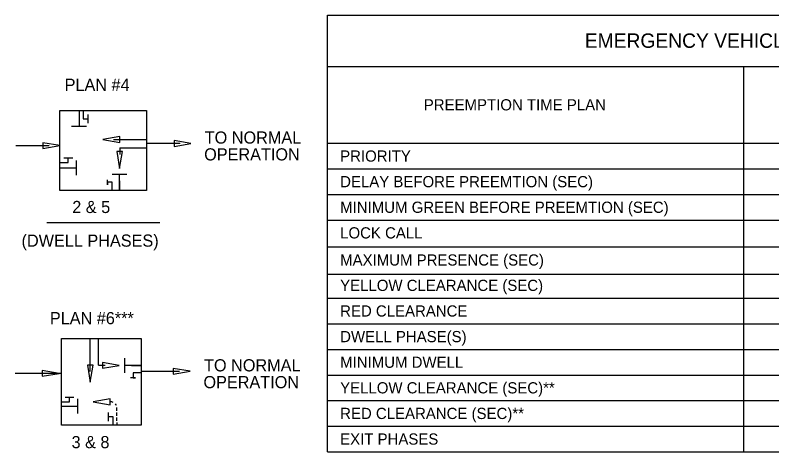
# Model space of a CAD drawing. Extents: x 0 to 1428, y -128 to 567.
# Drawn here: x 0.7203 to 1.0987, y 0.9823 to 1.2004 of the extents above; entities that cross this region are included whole.
import ezdxf

# ---------------------------------------------------------------- set-up
doc = ezdxf.new("R2010")
doc.units = 0
for name, color, linetype in [('SumBoxLines_dp', 7, 'Continuous'), ('TextLabel', 7, 'Continuous'), ('TextTables', 7, 'Continuous')]:
    doc.layers.add(name, color=color, linetype=linetype)

msp = doc.modelspace()

# ---------------------------------------------------------------- linework, layer by layer
at = {"layer": 'SumBoxLines_dp'}
for p, q in [((0.8764384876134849, 0.9822681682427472), (0.8764384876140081, 1.2004104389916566)), ((0.8764384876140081, 1.200410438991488), (1.3246048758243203, 1.200410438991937)), ((0.8764384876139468, 1.1748207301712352), (1.32460487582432, 1.1748207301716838)), ((1.0847013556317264, 0.9822681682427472), (1.0847013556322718, 1.1748207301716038)), ((0.8764384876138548, 1.1364361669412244), (1.32460487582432, 1.1364361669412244)), ((0.876438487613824, 1.1236413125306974), (1.1246852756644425, 1.1236413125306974)), ((0.8764384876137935, 1.110846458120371), (1.32460487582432, 1.110846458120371)), ((0.8764384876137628, 1.0980516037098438), (1.1646691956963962, 1.0980516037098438)), ((0.8764384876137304, 1.0846270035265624), (1.1246852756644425, 1.0846270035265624)), ((0.876438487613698, 1.0710904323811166), (1.1246852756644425, 1.0710904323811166)), ((0.8764384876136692, 1.0590372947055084), (1.32460487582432, 1.0590372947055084)), ((0.8764384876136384, 1.0462424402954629), (1.164669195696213, 1.0462424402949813)), ((0.8764384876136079, 1.0334475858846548), (1.32460487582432, 1.0334475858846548)), ((0.8764384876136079, 1.0334475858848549), (1.32460487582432, 1.0334475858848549)), ((0.8764384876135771, 1.020652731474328), (1.32460487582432, 1.020652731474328)), ((0.8764384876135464, 1.0078578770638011), (1.32460487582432, 1.0078578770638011)), ((0.8764384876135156, 0.9950630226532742), (1.3246048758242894, 0.9950630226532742)), ((0.8764384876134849, 0.9822681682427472), (1.3246048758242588, 0.9822681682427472))]:
    msp.add_line(p, q, dxfattribs=at)
at = {"layer": 'TextLabel'}
for p, q in [((0.7522504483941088, 1.152810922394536), (0.7522504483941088, 1.144769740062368)), ((0.754321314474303, 1.1527146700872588), (0.754321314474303, 1.1486660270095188)), ((0.756701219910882, 1.150841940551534), (0.756701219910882, 1.1464901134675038)), ((0.754321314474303, 1.1486660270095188), (0.756701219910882, 1.1486660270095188)), ((0.7559379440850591, 1.144769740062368), (0.7485629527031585, 1.144769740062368)), ((0.7694906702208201, 1.1383544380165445), (0.7861630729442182, 1.1383544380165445)), ((0.8028823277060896, 1.1362235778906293), (0.7862099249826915, 1.1362235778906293)), ((0.7373174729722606, 1.1351666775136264), (0.7206450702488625, 1.1351666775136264)), ((0.7726188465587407, 1.1341867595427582), (0.7861630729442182, 1.1341867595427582)), ((0.7726188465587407, 1.134128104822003), (0.7726188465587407, 1.1308028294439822)), ((0.7447219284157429, 1.1291997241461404), (0.7490737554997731, 1.1291997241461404)), ((0.746897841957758, 1.1268198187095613), (0.746897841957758, 1.1291997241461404)), ((0.7507733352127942, 1.1278014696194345), (0.7507733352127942, 1.1204264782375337)), ((0.7427321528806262, 1.124113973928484), (0.7507733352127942, 1.124113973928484)), ((0.7428491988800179, 1.1268198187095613), (0.746897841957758, 1.1268198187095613)), ((0.7688638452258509, 1.1209882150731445), (0.7762388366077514, 1.1209882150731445)), ((0.7725513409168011, 1.1129470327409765), (0.7725513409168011, 1.1209882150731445)), ((0.7664102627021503, 1.1156265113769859), (0.7664102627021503, 1.1181271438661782)), ((0.7687901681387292, 1.1169363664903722), (0.7664102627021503, 1.1169363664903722)), ((0.7664102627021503, 1.1169363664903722), (0.7664102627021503, 1.1156265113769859)), ((0.7687901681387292, 1.1128877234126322), (0.7687901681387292, 1.1169363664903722)), ((0.7725513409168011, 1.1176445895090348), (0.7725513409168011, 1.1128980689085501)), ((0.7360970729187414, 1.0967806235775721), (0.792625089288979, 1.0967806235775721)), ((0.7578390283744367, 1.0223741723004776), (0.7578390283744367, 1.0390465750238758)), ((0.7620067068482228, 1.0255023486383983), (0.7620067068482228, 1.0390465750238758)), ((0.7752052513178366, 1.0217473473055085), (0.7752052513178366, 1.029122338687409)), ((0.7620653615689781, 1.0255023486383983), (0.7653906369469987, 1.0255023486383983)), ((0.7832464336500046, 1.0254348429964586), (0.7752052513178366, 1.0254348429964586)), ((0.7785488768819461, 1.0254348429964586), (0.783295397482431, 1.0254348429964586)), ((0.8025341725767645, 1.0224479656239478), (0.783295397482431, 1.0224479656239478)), ((0.7434659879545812, 1.0213910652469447), (0.7202969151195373, 1.0213910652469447)), ((0.7805669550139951, 1.0192937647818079), (0.778066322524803, 1.0192937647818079)), ((0.7833057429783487, 1.0216736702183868), (0.7792570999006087, 1.0216736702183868)), ((0.7792570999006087, 1.0216736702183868), (0.7792570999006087, 1.0192937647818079)), ((0.7792570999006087, 1.0192937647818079), (0.7805669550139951, 1.0192937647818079)), ((0.7434787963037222, 1.0072048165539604), (0.7475274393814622, 1.0072048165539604)), ((0.7453515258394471, 1.0095847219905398), (0.7497033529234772, 1.0095847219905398)), ((0.7475274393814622, 1.0072048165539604), (0.7475274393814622, 1.0095847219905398)), ((0.7514237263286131, 1.0088214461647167), (0.7514237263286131, 1.0014464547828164)), ((0.7433825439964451, 1.0051339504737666), (0.7514237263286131, 1.0051339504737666)), ((0.7712376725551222, 1.0027047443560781), (0.7712376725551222, 1.0043536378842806)), ((0.7669937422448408, 0.9976054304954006), (0.7669937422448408, 1.0019572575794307)), ((0.7693736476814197, 0.9997813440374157), (0.7669937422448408, 0.9997813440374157)), ((0.7693736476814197, 0.9957327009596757), (0.7693736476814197, 0.9997813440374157)), ((0.7712376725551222, 1.000245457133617), (0.7712376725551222, 1.0018943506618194)), ((0.7712376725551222, 0.9977627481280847), (0.7712376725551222, 0.9994116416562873)), ((0.7712563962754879, 0.9955373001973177), (0.7712563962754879, 0.9969570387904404))]:
    msp.add_line(p, q, dxfattribs=at)
for points in [[(0.7860683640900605, 1.11289806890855), (0.7426537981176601, 1.11289806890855), (0.7426537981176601, 1.1527274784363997), (0.7860683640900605, 1.1527274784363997)], [(0.7641543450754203, 1.1382957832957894), (0.7726188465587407, 1.1368618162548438), (0.7726188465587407, 1.1397297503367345)], [(0.7426537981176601, 1.1352253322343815), (0.7341892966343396, 1.1366592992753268), (0.7341892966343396, 1.1337913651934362)], [(0.8082186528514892, 1.1362822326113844), (0.799754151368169, 1.13771619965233), (0.799754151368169, 1.134848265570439)], [(0.7725513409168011, 1.1238098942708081), (0.7739853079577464, 1.1322743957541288), (0.7711173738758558, 1.1322743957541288)], [(0.783295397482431, 1.0389518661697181), (0.783295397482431, 0.9955373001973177), (0.7434659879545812, 0.9955373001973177), (0.7434659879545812, 1.0389518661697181)], [(0.7723835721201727, 1.0254348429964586), (0.7639190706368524, 1.0268688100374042), (0.7639190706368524, 1.0240008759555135)], [(0.7423056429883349, 1.0214497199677), (0.7338411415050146, 1.022883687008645), (0.7338411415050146, 1.0200157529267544)], [(0.7578976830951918, 1.017037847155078), (0.7593316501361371, 1.0255023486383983), (0.7564637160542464, 1.0255023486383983)], [(0.8078704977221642, 1.0225066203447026), (0.7994059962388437, 1.0239405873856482), (0.7994059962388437, 1.0210726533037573)], [(0.7593269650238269, 1.0072343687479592), (0.7677914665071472, 1.005800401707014), (0.7677914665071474, 1.0086683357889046)]]:
    msp.add_lwpolyline(points, close=True, dxfattribs=at)
for start, end in [(66.80153166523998, 96.00238214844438), (23.21230037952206, 42.21240861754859)]:
    msp.add_arc((0.7681185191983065, 1.0041239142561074), 0.0031276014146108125, start, end, dxfattribs=at)

# ---------------------------------------------------------------- texts
for s, p in [('PLAN #4', (0.7450452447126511, 1.1625944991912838)), ('TO NORMAL', (0.8151180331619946, 1.1362436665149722)), ('OPERATION', (0.8148204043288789, 1.1278406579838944)), ('2 & 5', (0.7488744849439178, 1.1015634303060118)), ('(DWELL PHASES)', (0.7235126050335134, 1.084757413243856)), ('PLAN #6***', (0.7376643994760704, 1.0460350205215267)), ('TO NORMAL', (0.8147698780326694, 1.0224680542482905)), ('OPERATION', (0.814472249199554, 1.0140650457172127)), ('3 & 8', (0.748519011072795, 0.9840935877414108))]:
    msp.add_text(s, height=0.006069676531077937, dxfattribs=at).set_placement(p)
at = {"layer": 'TextTables'}
for s, height, p in [('EMERGENCY VEHICLE PREEMTION', 0.0071971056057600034, (1.005185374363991, 1.1840857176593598)), ('PREEMPTION TIME PLAN', 0.005597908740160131, (0.9246710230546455, 1.1528295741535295)), ('PRIORITY', 0.005597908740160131, (0.882835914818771, 1.1272398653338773)), ('DELAY BEFORE PREEMTION (SEC)', 0.005597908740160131, (0.882835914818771, 1.1144450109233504)), ('MINIMUM GREEN BEFORE PREEMTION (SEC)', 0.005597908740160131, (0.8828359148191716, 1.1016501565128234)), ('LOCK CALL', 0.005597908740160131, (0.882835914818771, 1.0888553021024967)), ('MAXIMUM PRESENCE (SEC)', 0.005597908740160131, (0.882835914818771, 1.075318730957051)), ('YELLOW CLEARANCE (SEC)', 0.005597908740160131, (0.8828359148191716, 1.0626358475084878)), ('RED CLEARANCE', 0.005597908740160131, (0.882835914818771, 1.0498409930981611)), ('DWELL PHASE(S)', 0.005597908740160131, (0.8828359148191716, 1.0370461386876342)), ('MINIMUM DWELL', 0.005597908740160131, (0.882835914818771, 1.0242512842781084)), ('YELLOW CLEARANCE (SEC)**', 0.005597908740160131, (0.8828359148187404, 1.0114564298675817)), ('RED CLEARANCE (SEC)**', 0.005597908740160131, (0.8828359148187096, 0.9986615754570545)), ('EXIT PHASES', 0.005597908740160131, (0.882835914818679, 0.9858667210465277))]:
    msp.add_text(s, height=height, dxfattribs=at).set_placement(p)

doc.saveas('drawing.dxf')
